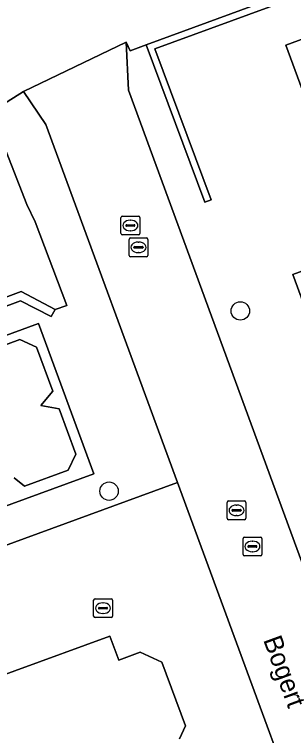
# Model space of a CAD drawing. Extents: x 160806 to 161707, y 383696 to 384148.
# Drawn here: x 160941.49 to 160956.33, y 383917.51 to 383955.96 of the extents above; entities that cross this region are included whole.
import ezdxf

# ---------------------------------------------------------------- set-up
doc = ezdxf.new("R2010")
doc.units = 0
for name, color, linetype in [('IMGEO_Boom', 7, 'Continuous'), ('IMGEO_Groenvoorziening', 7, 'Continuous'), ('IMGEO_Kolk', 7, 'Continuous'), ('IMGEO_Muur', 7, 'Continuous'), ('IMGEO_Openbare_ruimte_label', 7, 'Continuous'), ('IMGEO_Pand', 7, 'Continuous'), ('IMGEO_Rijbaan_lokaal_open', 7, 'Continuous'), ('IMGEO_Rioolput', 7, 'Continuous'), ('IMGEO_Voetpad_open', 7, 'Continuous')]:
    doc.layers.add(name, color=color, linetype=linetype)

msp = doc.modelspace()

# ---------------------------------------------------------------- linework, layer by layer
at = {"layer": 'IMGEO_Boom'}
for centre in [(160953.501, 383940.152), (160946.521, 383930.543)]:
    msp.add_circle(centre, 0.489, dxfattribs=at)
at = {"layer": 'IMGEO_Groenvoorziening'}
msp.add_lwpolyline([(160941.844, 383941.179), (160943.643, 383940.237), (160944.278, 383940.443), (160942.585, 383944.9), (160942.151, 383945.823), (160940.209, 383950.755), (160938.381, 383949.591), (160934.167, 383946.323), (160932.177, 383945.058), (160919.885, 383935.916), (160919.857, 383934.55), (160920.227, 383933.101)], close=True, dxfattribs=at)
at = {"layer": 'IMGEO_Kolk'}
for p, q in [((160947.153, 383944.28), (160947.153, 383945.132)), ((160947.228, 383945.206), (160948.08, 383945.206)), ((160947.641, 383944.986), (160947.666, 383944.986)), ((160948.154, 383945.132), (160948.154, 383944.28)), ((160947.412, 383944.7), (160947.412, 383944.712)), ((160947.85, 383944.663), (160947.452, 383944.663)), ((160947.455, 383944.749), (160947.853, 383944.749)), ((160947.896, 383944.712), (160947.896, 383944.7)), ((160948.08, 383944.206), (160947.228, 383944.206)), ((160947.664, 383944.426), (160947.639, 383944.426)), ((160952.799, 383929.095), (160952.799, 383929.947)), ((160952.874, 383930.021), (160953.726, 383930.021)), ((160953.8, 383929.947), (160953.8, 383929.095)), ((160953.058, 383929.515), (160953.058, 383929.527)), ((160953.101, 383929.564), (160953.499, 383929.564)), ((160953.287, 383929.801), (160953.312, 383929.801)), ((160953.542, 383929.527), (160953.542, 383929.515)), ((160953.496, 383929.478), (160953.098, 383929.478)), ((160953.31, 383929.241), (160953.285, 383929.241)), ((160953.726, 383929.021), (160952.874, 383929.021))]:
    msp.add_line(p, q, dxfattribs=at)
for points in [[(160947.153, 383944.28), (160947.153, 383945.132)], [(160947.228, 383945.206), (160948.08, 383945.206)], [(160948.154, 383945.132), (160948.154, 383944.28)], [(160948.08, 383944.206), (160947.228, 383944.206)], [(160952.799, 383929.095), (160952.799, 383929.947)], [(160952.874, 383930.021), (160953.726, 383930.021)], [(160953.8, 383929.947), (160953.8, 383929.095)], [(160953.726, 383929.021), (160952.874, 383929.021)]]:
    msp.add_lwpolyline(points, dxfattribs=at)
for centre, radius, start, end in [((160947.23, 383945.13), 0.0765, 91.552, 178.448), ((160947.23, 383945.13), 0.0765, 91.552, 178.448), ((160948.078, 383945.13), 0.0765, 1.552, 88.448), ((160948.078, 383945.13), 0.0765, 1.552, 88.448), ((160947.452, 383944.709), 0.0403, 85.8775, 175.7526), ((160947.449, 383944.699), 0.0366, 178.938, 274.7102), ((160947.853, 383944.706), 0.043, 264.8664, 352.4533), ((160947.857, 383944.711), 0.0386, 1.7309, 96.639), ((160947.23, 383944.282), 0.0765, 181.552, 268.448), ((160947.23, 383944.282), 0.0765, 181.552, 268.448), ((160948.078, 383944.282), 0.0765, 271.552, 358.448), ((160948.078, 383944.282), 0.0765, 271.552, 358.448), ((160952.876, 383929.945), 0.0765, 91.552, 178.448), ((160952.876, 383929.945), 0.0765, 91.552, 178.448), ((160953.724, 383929.945), 0.0765, 1.552, 88.448), ((160953.724, 383929.945), 0.0765, 1.552, 88.448), ((160953.098, 383929.524), 0.0403, 85.8775, 175.7526), ((160953.095, 383929.514), 0.0366, 178.938, 274.7102), ((160953.499, 383929.521), 0.043, 264.8664, 352.4533), ((160953.503, 383929.526), 0.0386, 1.7309, 96.639), ((160952.876, 383929.097), 0.0765, 181.552, 268.448), ((160952.876, 383929.097), 0.0765, 181.552, 268.448), ((160953.724, 383929.097), 0.0765, 271.552, 358.448), ((160953.724, 383929.097), 0.0765, 271.552, 358.448)]:
    msp.add_arc(centre, radius, start, end, dxfattribs=at)
for centre, major_axis, ratio, start_param, end_param in [((160947.64, 383944.706), (-0.387, 0.002), 0.722429, 4.712389, 7.853982), ((160947.665, 383944.706), (-0.39, 0.002), 0.717154, 1.570796, 4.712389), ((160953.286, 383929.521), (-0.387, 0.002), 0.722429, 4.712389, 7.853982), ((160953.311, 383929.521), (-0.39, 0.002), 0.717154, 1.570796, 4.712389)]:
    msp.add_ellipse(centre, major_axis=major_axis, ratio=ratio, start_param=start_param, end_param=end_param, dxfattribs=at)
at = {"layer": 'IMGEO_Muur'}
for points in [[(160951.608, 383945.945), (160951.945, 383946.07), (160948.954, 383954.127), (160962.106, 383958.967), (160961.982, 383959.305), (160961.285, 383959.048), (160948.491, 383954.34)], [(160943.643, 383940.237), (160941.844, 383941.179), (160920.227, 383933.101), (160919.501, 383932.83), (160919.628, 383932.473), (160920.785, 383929.199), (160921.2, 383929.346), (160920.06, 383932.569), (160941.814, 383940.698), (160943.439, 383939.847)]]:
    msp.add_lwpolyline(points, close=True, dxfattribs=at)
at = {"layer": 'IMGEO_Pand'}
for points in [[(160958.56, 383955.294), (160955.925, 383954.326), (160957.713, 383949.459)], [(160959.797, 383943.383), (160956.293, 383942.096), (160964.049, 383920.98)], [(160941.476, 383931.249), (160942.013, 383930.801), (160944.35, 383931.659), (160944.749, 383932.52), (160943.86, 383934.941), (160942.894, 383935.109), (160943.526, 383935.866), (160942.662, 383938.218), (160941.767, 383938.632), (160939.406, 383937.765)], [(160950.257, 383917.338), (160950.577, 383918.029), (160949.333, 383921.418), (160948.181, 383921.951), (160947.032, 383921.529), (160946.56, 383922.813), (160941.514, 383920.961), (160938.698, 383919.927), (160934.836, 383918.509), (160934.251, 383918.294), (160933.804, 383919.512), (160932.872, 383919.943), (160929.533, 383918.717), (160929.143, 383917.874), (160932.92, 383907.588)]]:
    msp.add_lwpolyline(points, dxfattribs=at)
at = {"layer": 'IMGEO_Rijbaan_lokaal_open'}
msp.add_lwpolyline([(160943.158, 383950.097), (160950.161, 383931.007), (160960.137, 383903.811), (160959.806, 383902.516), (160968.05, 383879.828), (160984.869, 383885.974), (160986.341, 383885.715), (160990.275, 383885.032), (160991.432, 383884.817), (161000, 383887.972), (161034.783, 383900.781), (161033.437, 383904.394), (161000, 383892.005), (160990.074, 383888.326), (160982.677, 383889.672), (160974.531, 383886.634), (160974.125, 383886.483), (160971.037, 383887.859), (160947.548, 383951.917), (160947.428, 383954.476), (160941.963, 383951.859)], close=True, dxfattribs=at)
at = {"layer": 'IMGEO_Rioolput'}
for p, q in [((160947.581, 383943.116), (160947.581, 383943.968)), ((160947.656, 383944.042), (160948.508, 383944.042)), ((160948.069, 383943.822), (160948.094, 383943.822)), ((160948.582, 383943.968), (160948.582, 383943.116)), ((160947.84, 383943.536), (160947.84, 383943.548)), ((160948.278, 383943.499), (160947.88, 383943.499)), ((160947.883, 383943.585), (160948.281, 383943.585)), ((160948.324, 383943.548), (160948.324, 383943.536)), ((160948.508, 383943.042), (160947.656, 383943.042)), ((160948.092, 383943.262), (160948.067, 383943.262)), ((160953.645, 383927.169), (160953.645, 383928.021)), ((160953.72, 383928.095), (160954.572, 383928.095)), ((160954.646, 383928.021), (160954.646, 383927.169)), ((160953.904, 383927.589), (160953.904, 383927.601)), ((160953.947, 383927.638), (160954.345, 383927.638)), ((160954.133, 383927.875), (160954.158, 383927.875)), ((160954.388, 383927.601), (160954.388, 383927.589)), ((160954.342, 383927.552), (160953.944, 383927.552)), ((160954.156, 383927.315), (160954.131, 383927.315)), ((160954.572, 383927.095), (160953.72, 383927.095)), ((160945.696, 383923.879), (160945.696, 383924.731)), ((160945.771, 383924.805), (160946.623, 383924.805)), ((160946.184, 383924.585), (160946.209, 383924.585)), ((160946.697, 383924.731), (160946.697, 383923.879)), ((160945.955, 383924.299), (160945.955, 383924.311)), ((160946.393, 383924.262), (160945.995, 383924.262)), ((160945.998, 383924.348), (160946.396, 383924.348)), ((160946.439, 383924.311), (160946.439, 383924.299)), ((160946.623, 383923.805), (160945.771, 383923.805)), ((160946.207, 383924.025), (160946.182, 383924.025))]:
    msp.add_line(p, q, dxfattribs=at)
for points in [[(160947.581, 383943.116), (160947.581, 383943.968)], [(160947.656, 383944.042), (160948.508, 383944.042)], [(160948.582, 383943.968), (160948.582, 383943.116)], [(160948.508, 383943.042), (160947.656, 383943.042)], [(160953.645, 383927.169), (160953.645, 383928.021)], [(160953.72, 383928.095), (160954.572, 383928.095)], [(160954.646, 383928.021), (160954.646, 383927.169)], [(160954.572, 383927.095), (160953.72, 383927.095)], [(160945.696, 383923.879), (160945.696, 383924.731)], [(160945.771, 383924.805), (160946.623, 383924.805)], [(160946.697, 383924.731), (160946.697, 383923.879)], [(160946.623, 383923.805), (160945.771, 383923.805)]]:
    msp.add_lwpolyline(points, dxfattribs=at)
for centre, radius, start, end in [((160947.658, 383943.966), 0.0765, 91.552, 178.448), ((160947.658, 383943.966), 0.0765, 91.552, 178.448), ((160948.506, 383943.966), 0.0765, 1.552, 88.448), ((160948.506, 383943.966), 0.0765, 1.552, 88.448), ((160947.88, 383943.545), 0.0403, 85.8775, 175.7526), ((160947.877, 383943.535), 0.0366, 178.938, 274.7102), ((160948.281, 383943.542), 0.043, 264.8664, 352.4533), ((160948.285, 383943.547), 0.0386, 1.7309, 96.639), ((160947.658, 383943.118), 0.0765, 181.552, 268.448), ((160947.658, 383943.118), 0.0765, 181.552, 268.448), ((160948.506, 383943.118), 0.0765, 271.552, 358.448), ((160948.506, 383943.118), 0.0765, 271.552, 358.448), ((160953.722, 383928.019), 0.0765, 91.552, 178.448), ((160953.722, 383928.019), 0.0765, 91.552, 178.448), ((160954.57, 383928.019), 0.0765, 1.552, 88.448), ((160954.57, 383928.019), 0.0765, 1.552, 88.448), ((160953.944, 383927.598), 0.0403, 85.8775, 175.7526), ((160953.941, 383927.588), 0.0366, 178.938, 274.7102), ((160954.345, 383927.595), 0.043, 264.8664, 352.4533), ((160954.349, 383927.6), 0.0386, 1.7309, 96.639), ((160953.722, 383927.171), 0.0765, 181.552, 268.448), ((160953.722, 383927.171), 0.0765, 181.552, 268.448), ((160954.57, 383927.171), 0.0765, 271.552, 358.448), ((160954.57, 383927.171), 0.0765, 271.552, 358.448), ((160945.773, 383924.729), 0.0765, 91.552, 178.448), ((160945.773, 383924.729), 0.0765, 91.552, 178.448), ((160946.621, 383924.729), 0.0765, 1.552, 88.448), ((160946.621, 383924.729), 0.0765, 1.552, 88.448), ((160945.995, 383924.308), 0.0403, 85.8775, 175.7526), ((160945.992, 383924.298), 0.0366, 178.938, 274.7102), ((160946.396, 383924.305), 0.043, 264.8664, 352.4533), ((160946.4, 383924.31), 0.0386, 1.7309, 96.639), ((160945.773, 383923.881), 0.0765, 181.552, 268.448), ((160945.773, 383923.881), 0.0765, 181.552, 268.448), ((160946.621, 383923.881), 0.0765, 271.552, 358.448), ((160946.621, 383923.881), 0.0765, 271.552, 358.448)]:
    msp.add_arc(centre, radius, start, end, dxfattribs=at)
for centre, major_axis, ratio, start_param, end_param in [((160948.068, 383943.542), (-0.387, 0.002), 0.722429, 4.712389, 7.853982), ((160948.093, 383943.542), (-0.39, 0.002), 0.717154, 1.570796, 4.712389), ((160954.132, 383927.595), (-0.387, 0.002), 0.722429, 4.712389, 7.853982), ((160954.157, 383927.595), (-0.39, 0.002), 0.717154, 1.570796, 4.712389), ((160946.183, 383924.305), (-0.387, 0.002), 0.722429, 4.712389, 7.853982), ((160946.208, 383924.305), (-0.39, 0.002), 0.717154, 1.570796, 4.712389)]:
    msp.add_ellipse(centre, major_axis=major_axis, ratio=ratio, start_param=start_param, end_param=end_param, dxfattribs=at)
at = {"layer": 'IMGEO_Voetpad_open'}
for points in [[(160930.868, 383948.143), (160928.691, 383946.466), (160915.435, 383936.839), (160917.241, 383931.994), (160917.656, 383932.175), (160917.798, 383931.792), (160919.628, 383932.473), (160919.501, 383932.83), (160920.227, 383933.101), (160919.857, 383934.55), (160919.885, 383935.916), (160932.177, 383945.058), (160934.167, 383946.323), (160938.381, 383949.591), (160940.209, 383950.755), (160941.963, 383951.859), (160947.428, 383954.476), (160947.637, 383954.018), (160948.491, 383954.34), (160961.285, 383959.048), (160961.058, 383959.607), (160959.525, 383959.063)], [(160962.106, 383958.967), (160948.954, 383954.127), (160951.945, 383946.07), (160951.608, 383945.945), (160948.491, 383954.34), (160947.637, 383954.018), (160947.428, 383954.476), (160947.548, 383951.917), (160971.037, 383887.859)], [(160957.713, 383949.459), (160955.925, 383954.326), (160958.56, 383955.294)], [(160964.049, 383920.98), (160956.293, 383942.096), (160959.797, 383943.383)], [(160939.406, 383937.765), (160941.767, 383938.632), (160942.662, 383938.218), (160943.526, 383935.866), (160942.894, 383935.109), (160943.86, 383934.941), (160944.749, 383932.52), (160944.35, 383931.659), (160942.013, 383930.801), (160941.476, 383931.249)], [(160960.137, 383903.811), (160950.161, 383931.007), (160921.944, 383920.655), (160925.013, 383912.411), (160926.853, 383913.016), (160930.971, 383901.988), (160934.751, 383903.36), (160939.722, 383889.883), (160939.309, 383889.731), (160934.489, 383902.797), (160932.668, 383902.136), (160933.165, 383900.776), (160933.578, 383900.927), (160938.39, 383887.768), (160939.444, 383888.153), (160943.859, 383876.128), (160945.05, 383876.564), (160950.202, 383862.823), (160953.064, 383863.812), (160955.689, 383856.974), (160961.572, 383859.068)], [(160932.92, 383907.588), (160929.143, 383917.874), (160929.533, 383918.717), (160932.872, 383919.943), (160933.804, 383919.512), (160934.251, 383918.294), (160934.836, 383918.509), (160938.698, 383919.927), (160941.514, 383920.961), (160946.56, 383922.813), (160947.032, 383921.529), (160948.181, 383921.951), (160949.333, 383921.418), (160950.577, 383918.029), (160950.257, 383917.338)]]:
    msp.add_lwpolyline(points, dxfattribs=at)
for points in [[(160943.158, 383950.097), (160941.963, 383951.859), (160940.209, 383950.755), (160942.151, 383945.823), (160942.585, 383944.9), (160944.278, 383940.443), (160943.643, 383940.237), (160943.439, 383939.847), (160941.814, 383940.698), (160920.06, 383932.569), (160921.2, 383929.346), (160920.785, 383929.199), (160919.628, 383932.473), (160917.798, 383931.792), (160921.944, 383920.655), (160950.161, 383931.007)], [(160945.701, 383931.469), (160942.761, 383939.477), (160928.019, 383934.065), (160930.959, 383926.057)], [(160928.019, 383934.065), (160942.761, 383939.477), (160945.701, 383931.469), (160930.959, 383926.057)]]:
    msp.add_lwpolyline(points, close=True, dxfattribs=at)

# ---------------------------------------------------------------- texts
at = {"layer": 'IMGEO_Openbare_ruimte_label'}
msp.add_text('Bogert', height=1, rotation=290.1202, dxfattribs=at).set_placement((160954.705, 383922.619))

doc.saveas('drawing.dxf')
